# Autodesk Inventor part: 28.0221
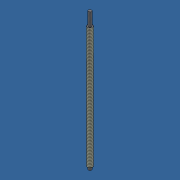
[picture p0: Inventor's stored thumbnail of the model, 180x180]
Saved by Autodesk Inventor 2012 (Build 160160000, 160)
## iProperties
Created: 2007-06
Part Number: 28.0221
Document SubType Name: Modeling
Designer: Andy Moles
Density: 1 g/cm^3
Mass: 82.8674 g
Surface Area: 217.38 cm^2
Volume: 82.8674 cm^3
Description: L = TRAVEL + 5.483" MACHINE TO PRINT 28.0221
Stock Number: 28.0202 ACME SCREW 16X4 RH
Catalog Web Link: F
Vendor: F
Material: Default
Author: Andy Moles
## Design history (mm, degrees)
sketch "Sketch1"
  geometry: C1 r 8 at (0, 0); 1 further point
  constraints: 1 centre point, 1 coincident
  dimensions: "d0" = 16 diameter of C1
extrude "Extrusion1" new body sketch "Sketch1" stored distance "d1" = 392.52 (computed from TRAVEL); taper "d2" = 0 deg
thread "Thread1" dims "d3" = 10, "d4" = 0
sketch "Sketch2"
  geometry: C1 r 8 at (0, 0) reference; C2 r 4.975 at (0, 0)
  constraints: 1 centre point, 1 coincident
  dimensions: "d5" = 9.95 diameter of C2
extrude "Extrusion2" join sketch "Sketch2" distance "d6" = 42.415; taper "d7" = 0 deg
sketch "Sketch3"
  geometry: C1 r 8 at (0, 0) reference; C2 r 5 at (0, 0)
  constraints: 1 centre point, 1 coincident
  dimensions: "d8" = 10 diameter of C2
extrude "Extrusion3" join sketch "Sketch3" distance "d9" = 9.14; taper "d10" = 0 deg
sketch "Sketch4"
  geometry: L1 (-2.646, 4.213)-(2.646, 4.213); A1 r 4.975 centre (0, 0) between (2.646, 4.213) and (-2.646, 4.213); 2 further points
  constraints: 2 end point, 2 point on circle, 1 centre point, 1 coincident, 1 horizontal, 1 midpoint, 1 vertical alignment, 2 other
  dimensions: "d12" = 0.762 dimension on L1
extrude "Extrusion4" cut sketch "Sketch4" distance "d13" = 25.4; taper "d14" = 0 deg
body "Solid1"
other parameters: "TRAVEL" = 304.8 [user parameter; used in 1 equation term]
